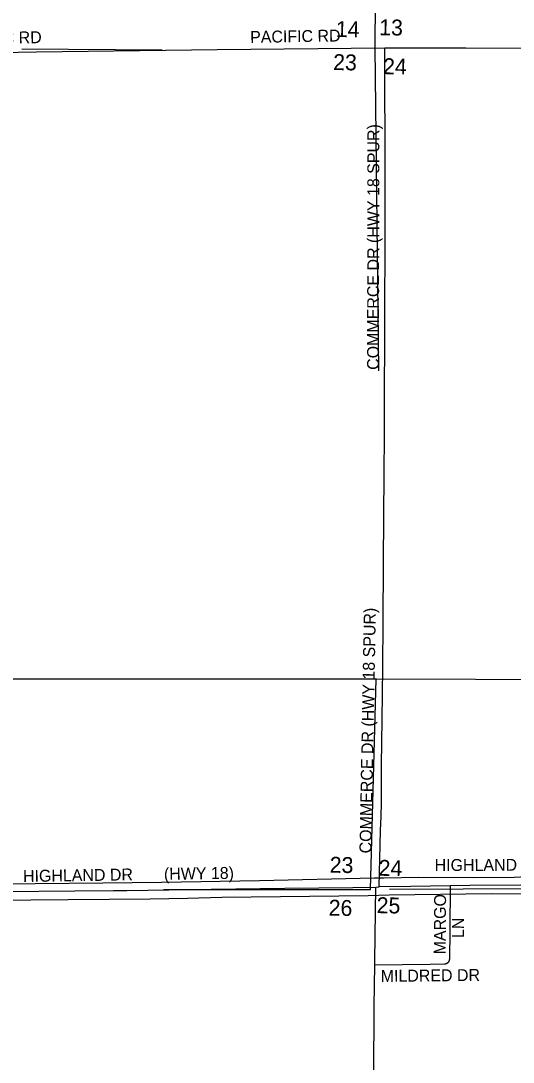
# Model space of a CAD drawing. Extents: x 1670563 to 1761545, y 515755 to 578944.
# Drawn here: x 1717981 to 1721077, y 543183 to 549724 of the extents above; entities that cross this region are included whole.
import ezdxf

# ---------------------------------------------------------------- set-up
doc = ezdxf.new("R2010")
doc.units = 0
for name, color, linetype in [('5_sectionlines', 7, 'Continuous'), ('62_text', 7, 'Continuous'), ('SHP_LINE', 7, 'Continuous'), ('STREETCL', 7, 'Continuous'), ('STRNAMES', 7, 'Continuous')]:
    doc.layers.add(name, color=color, linetype=linetype)

msp = doc.modelspace()

# ---------------------------------------------------------------- linework, layer by layer
at = {"layer": '5_sectionlines'}
for p, q in [((1717987.4, 549548.9), (1718869.3, 549542.7)), ((1720178.8, 544268.3), (1720215.7, 545589)), ((1718879, 544267.9), (1720178.8, 544268.3)), ((1720298.5, 544270.6), (1725340.1, 544283.3))]:
    msp.add_line(p, q, dxfattribs=at)
msp.add_lwpolyline([(1720231.1, 547525.9), (1720208.5, 549556.8), (1720246.3, 554813.4), (1720383.9, 560096.2), (1720455.1, 565306)], dxfattribs=at)
at = {"layer": 'SHP_LINE'}
for points in [[(1717630, 545590), (1720217, 545592), (1721462, 545587), (1721530, 545562), (1721575, 545530)], [(1721603, 544364), (1721484, 544358), (1721422, 544358), (1721243, 544351), (1721084, 544344), (1720825, 544340), (1720483, 544343), (1720264, 544339), (1720205, 544338), (1719482, 544323), (1718865, 544312), (1718496, 544308), (1717643, 544299), (1717373, 544300), (1717142, 544300), (1716700, 544299), (1716330, 544299), (1715854, 544292), (1715537, 544295), (1715269, 544296), (1715178, 544297), (1715220, 544183)], [(1715818, 544193), (1716433, 544193), (1716859, 544195), (1717570, 544198), (1718279, 544205), (1718794, 544209), (1719030, 544214), (1719245, 544220), (1720165, 544229), (1720298, 544234), (1720940, 544243), (1721558, 544236)]]:
    msp.add_lwpolyline(points, dxfattribs=at)
at = {"layer": 'STREETCL'}
for points in [[(1717196, 549514.1), (1717614.9, 549521.7), (1718079.6, 549529.3), (1719214.7, 549544), (1720269.4, 549554.8)], [(1720233.7, 544283.4), (1720243.4, 544638.7), (1720246.9, 544725.5), (1720248.4, 544812.4), (1720249.8, 545050.3), (1720254.1, 545333.2), (1720257.7, 545660.5), (1720258.4, 545949.2), (1720261.3, 546316), (1720264.1, 546616), (1720264.8, 546873.2), (1720267, 547128.9), (1720267.7, 547431.3), (1720269.2, 547672), (1720270.6, 547969.2), (1720271.3, 548258.8), (1720271.3, 548535.4), (1720272, 548999.3), (1720269.8, 549286.1), (1720269.1, 549509.9), (1720269.4, 549554.8)], [(1720269.4, 549554.8), (1720523.3, 549555.4), (1720778.3, 549555.5), (1721184.1, 549552.6), (1721377, 549550.4), (1721420.1, 549550.5), (1721463.1, 549551.7), (1721506.1, 549554), (1721543, 549556.1), (1721567.9, 549557), (1721592.9, 549557.2), (1721617.9, 549556.8), (1721894.6, 549557.5), (1722319.5, 549561.9), (1722652.4, 549565.5), (1722863.2, 549567.6), (1723213.1, 549571.9), (1723410.3, 549571.8), (1723420.8, 549571.9)], [(1717608.2, 544254.2), (1717869.9, 544255.3), (1718320.7, 544258.7), (1718562.8, 544261), (1718647.1, 544261.8), (1719178.2, 544270.6), (1719642.1, 544276.2), (1720069.5, 544281), (1720212.4, 544283)], [(1720207.5, 543792), (1720207.9, 543819.9), (1720212.4, 544283)], [(1720212.4, 544283), (1720233.7, 544283.4)], [(1722848.9, 544314.1), (1722428.8, 544308.1), (1721994.1, 544303.8), (1721601.4, 544298.8), (1721124.3, 544294.5), (1720803.9, 544293), (1720433, 544286.6), (1720233.7, 544283.4)], [(1720680, 544290.9), (1720678.2, 544013.2), (1720675.6, 543830.2), (1720675.6, 543829.1), (1720675.5, 543828.1), (1720675.4, 543827), (1720675.3, 543825.9), (1720675.1, 543824.9), (1720674.9, 543823.8), (1720674.7, 543822.7), (1720674.4, 543821.7), (1720674.1, 543820.7), (1720673.8, 543819.6), (1720673.4, 543818.6), (1720673, 543817.6), (1720672.5, 543816.6), (1720672.1, 543815.7), (1720671.6, 543814.7), (1720671, 543813.8), (1720670.4, 543812.9), (1720669.8, 543812), (1720669.2, 543811.1), (1720668.5, 543810.3), (1720667.8, 543809.4), (1720667.1, 543808.6), (1720666.4, 543807.9)], [(1720666.4, 543807.9), (1720665.6, 543807.1), (1720664.8, 543806.4), (1720664, 543805.7), (1720663.1, 543805), (1720662.2, 543804.4), (1720661.3, 543803.8), (1720660.4, 543803.2), (1720659.5, 543802.7), (1720658.5, 543802.2), (1720657.6, 543801.7), (1720656.6, 543801.2), (1720655.6, 543800.8), (1720654.6, 543800.5), (1720653.6, 543800.1), (1720652.5, 543799.8), (1720651.5, 543799.5), (1720650.4, 543799.3), (1720649.4, 543799.1), (1720648.3, 543798.9), (1720647.2, 543798.8), (1720646.2, 543798.7), (1720645.1, 543798.7), (1720644, 543798.7), (1720554, 543797.1), (1720207.5, 543792)], [(1720175.7, 541374), (1720184.6, 541926.2), (1720192.5, 542530.1), (1720200.5, 543097.3), (1720203.7, 543535.3), (1720207.5, 543792)]]:
    msp.add_lwpolyline(points, dxfattribs=at)

# ---------------------------------------------------------------- texts
at = {"layer": '62_text'}
for s, rotation, p in [('14', 358.93013, (1719961.2, 549623)), ('13', 358.93013, (1720233.8, 549634.4)), ('23', 358.93016, (1719944.2, 549415.6)), ('24', 358.93015, (1720258.2, 549389.8)), ('23', 358.93102, (1719922.6, 544373.5)), ('24', 358.93102, (1720230, 544354.2)), ('26', 358.93105, (1719916, 544103.7)), ('25', 358.93105, (1720217.7, 544119.5))]:
    msp.add_text(s, height=100, rotation=rotation, dxfattribs=at).set_placement(p)
at = {"layer": 'STRNAMES'}
for s, rotation, p in [('PACIFIC RD', 0.99847, (1717544.7, 549574.7)), ('PACIFIC RD', 0.99847, (1719423.6, 549585.2)), ('COMMERCE DR (HWY 18 SPUR)', 89.91449, (1720233.2, 547532)), ('COMMERCE DR (HWY 18 SPUR)', 88.94061, (1720185, 544493.9)), ('HIGHLAND DR (HWY 18)', 0.16695, (1720583.2, 544383.8)), ('HIGHLAND DR       (HWY 18)', 0.88147, (1717995.6, 544314.6)), ('MARGO', 89.66504, (1720652.7, 543859.9)), ('LN', 89.66504, (1720767.5, 543962.8)), ('MILDRED DR', 0.61294, (1720244.5, 543686.8))]:
    msp.add_text(s, height=75, rotation=rotation, dxfattribs=at).set_placement(p)

doc.saveas('drawing.dxf')
